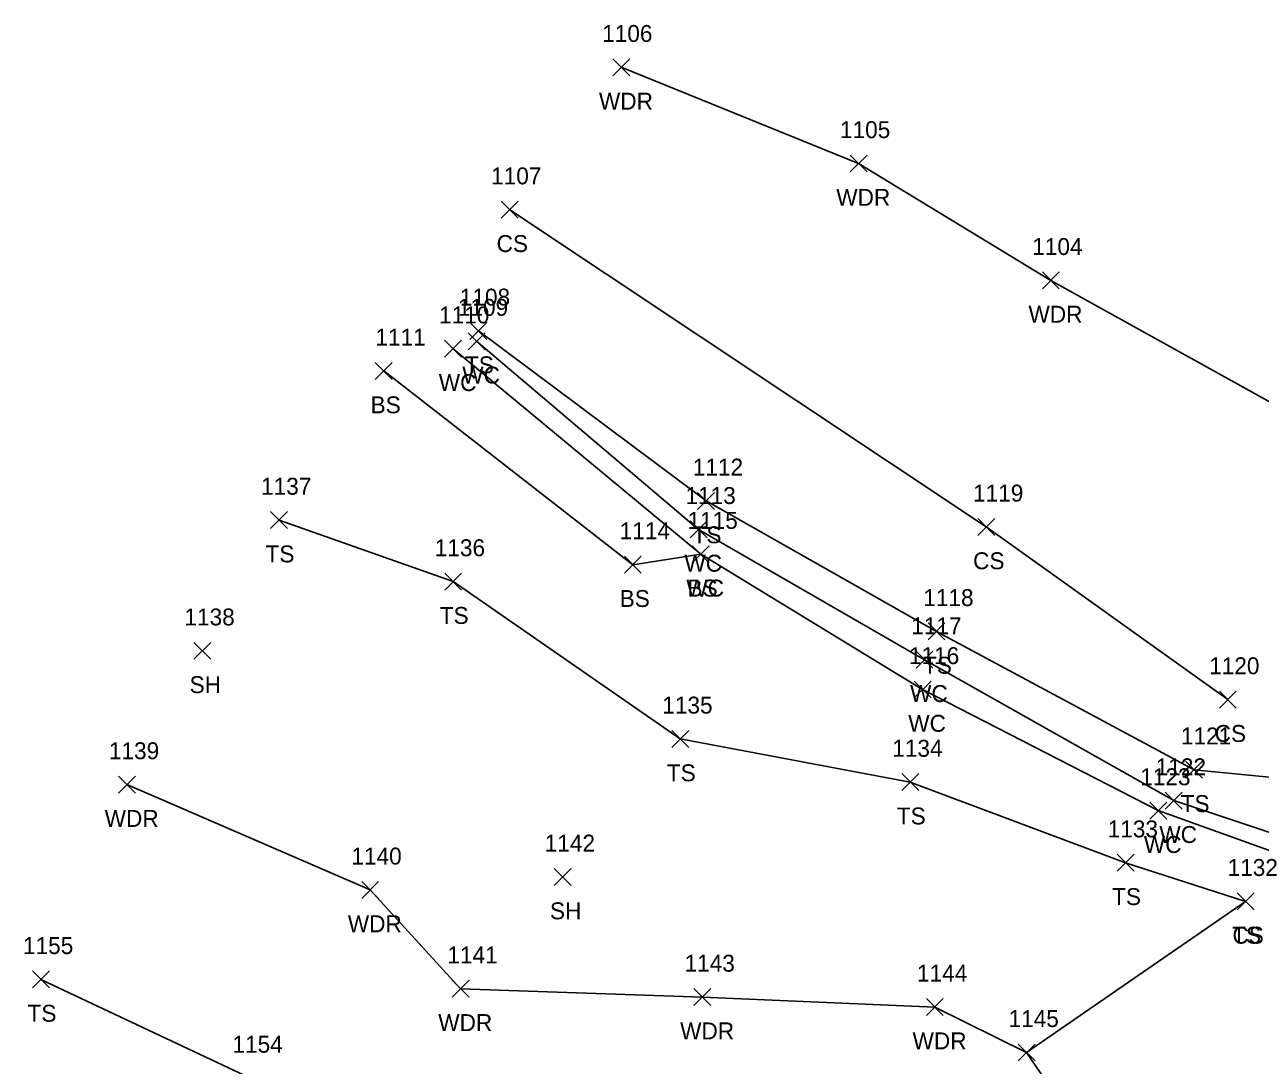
# Model space of a CAD drawing. Extents: x 1640777 to 1641692, y 610911 to 611377.
# Drawn here: x 1641273.4 to 1641419.5, y 611254.1 to 611377.1 of the extents above; entities that cross this region are included whole.
import ezdxf

# ---------------------------------------------------------------- set-up
doc = ezdxf.new("R2010")
doc.units = 0
for name, color, linetype in [('L_A', 7, 'Continuous'), ('L_I', 7, 'Continuous'), ('L_TIC', 7, 'Continuous'), ('LAWA', 7, 'Continuous'), ('LAWE', 7, 'Continuous'), ('LELB', 7, 'Continuous')]:
    doc.layers.add(name, color=color, linetype=linetype)

msp = doc.modelspace()

# ---------------------------------------------------------------- linework, layer by layer
at = {"layer": 'L_TIC'}
for points in [[(1641342.92, 611371.04), (1641344.92, 611373.04)], [(1641344.92, 611371.04), (1641342.92, 611373.04)], [(1641370.98, 611359.67), (1641372.98, 611361.67)], [(1641372.98, 611359.67), (1641370.98, 611361.67)], [(1641329.74, 611354.21), (1641331.74, 611356.21)], [(1641331.74, 611354.21), (1641329.74, 611356.21)], [(1641393.71, 611345.86), (1641395.71, 611347.86)], [(1641395.71, 611345.86), (1641393.71, 611347.86)], [(1641326.03, 611339.88), (1641328.03, 611341.88)], [(1641328.03, 611339.88), (1641326.03, 611341.88)], [(1641325.81, 611338.67), (1641327.81, 611340.67)], [(1641327.81, 611338.67), (1641325.81, 611340.67)], [(1641323.03, 611337.78), (1641325.03, 611339.78)], [(1641325.03, 611337.78), (1641323.03, 611339.78)], [(1641314.84, 611335.15), (1641316.84, 611337.15)], [(1641316.84, 611335.15), (1641314.84, 611337.15)], [(1641352.94, 611319.79), (1641354.94, 611321.79)], [(1641354.94, 611319.79), (1641352.94, 611321.79)], [(1641302.46, 611317.53), (1641304.46, 611319.53)], [(1641304.46, 611317.53), (1641302.46, 611319.53)], [(1641352.07, 611316.43), (1641354.07, 611318.43)], [(1641354.07, 611316.43), (1641352.07, 611318.43)], [(1641386.08, 611316.72), (1641388.08, 611318.72)], [(1641388.08, 611316.72), (1641386.08, 611318.72)], [(1641352.31, 611313.49), (1641354.31, 611315.49)], [(1641354.31, 611313.49), (1641352.31, 611315.49)], [(1641352.31, 611313.49), (1641354.31, 611315.49)], [(1641354.31, 611313.49), (1641352.31, 611315.49)], [(1641344.29, 611312.26), (1641346.29, 611314.26)], [(1641346.29, 611312.26), (1641344.29, 611314.26)], [(1641323.05, 611310.26), (1641325.05, 611312.26)], [(1641325.05, 611310.26), (1641323.05, 611312.26)], [(1641380.19, 611304.37), (1641382.19, 611306.37)], [(1641382.19, 611304.37), (1641380.19, 611306.37)], [(1641293.39, 611302.08), (1641295.39, 611304.08)], [(1641295.39, 611302.08), (1641293.39, 611304.08)], [(1641378.77, 611301.03), (1641380.77, 611303.03)], [(1641380.77, 611301.03), (1641378.77, 611303.03)], [(1641378.55, 611297.51), (1641380.55, 611299.51)], [(1641380.55, 611297.51), (1641378.55, 611299.51)], [(1641414.64, 611296.31), (1641416.64, 611298.31)], [(1641416.64, 611296.31), (1641414.64, 611298.31)], [(1641349.9, 611291.66), (1641351.9, 611293.66)], [(1641351.9, 611291.66), (1641349.9, 611293.66)], [(1641410.65, 611288.02), (1641412.65, 611290.02)], [(1641412.65, 611288.02), (1641410.65, 611290.02)], [(1641284.47, 611286.27), (1641286.47, 611288.27)], [(1641286.47, 611286.27), (1641284.47, 611288.27)], [(1641377.09, 611286.56), (1641379.09, 611288.56)], [(1641379.09, 611286.56), (1641377.09, 611288.56)], [(1641408.24, 611284.37), (1641410.24, 611286.37)], [(1641410.24, 611284.37), (1641408.24, 611286.37)], [(1641406.41, 611283.19), (1641408.41, 611285.19)], [(1641408.41, 611283.19), (1641406.41, 611285.19)], [(1641402.55, 611277.03), (1641404.55, 611279.03)], [(1641404.55, 611277.03), (1641402.55, 611279.03)], [(1641336, 611275.35), (1641338, 611277.35)], [(1641338, 611275.35), (1641336, 611277.35)], [(1641313.23, 611273.82), (1641315.23, 611275.82)], [(1641315.23, 611273.82), (1641313.23, 611275.82)], [(1641416.74, 611272.47), (1641418.74, 611274.47)], [(1641418.74, 611272.47), (1641416.74, 611274.47)], [(1641416.74, 611272.47), (1641418.74, 611274.47)], [(1641418.74, 611272.47), (1641416.74, 611274.47)], [(1641274.31, 611263.24), (1641276.31, 611265.24)], [(1641276.31, 611263.24), (1641274.31, 611265.24)], [(1641323.92, 611262.14), (1641325.92, 611264.14)], [(1641325.92, 611262.14), (1641323.92, 611264.14)], [(1641352.52, 611261.16), (1641354.52, 611263.16)], [(1641354.52, 611261.16), (1641352.52, 611263.16)], [(1641380, 611259.98), (1641382, 611261.98)], [(1641382, 611259.98), (1641380, 611261.98)], [(1641390.84, 611254.61), (1641392.84, 611256.61)], [(1641392.84, 611254.61), (1641390.84, 611256.61)], [(1641390.84, 611254.61), (1641392.84, 611256.61)], [(1641392.84, 611254.61), (1641390.84, 611256.61)]]:
    msp.add_lwpolyline(points, dxfattribs=at)
at = {"layer": 'LAWA'}
for points in [[(1641436.08, 611316.38), (1641422.14, 611331.65), (1641394.71, 611346.86), (1641371.98, 611360.67), (1641343.92, 611372.04)], [(1641285.47, 611287.27), (1641314.23, 611274.82), (1641324.92, 611263.14), (1641353.52, 611262.16), (1641381, 611260.98), (1641391.84, 611255.61), (1641400.01, 611243.67), (1641389.74, 611233.78), (1641364.25, 611234.98), (1641344.03, 611214.73), (1641310.82, 611201.14), (1641274.29, 611183.81)]]:
    msp.add_lwpolyline(points, dxfattribs=at)
at = {"layer": 'LAWE'}
for points in [[(1641324.03, 611338.78), (1641353.31, 611314.49), (1641379.55, 611298.51), (1641407.41, 611284.19), (1641421.99, 611278.95)], [(1641326.81, 611339.67), (1641353.07, 611317.43), (1641379.77, 611302.03), (1641409.24, 611285.37), (1641422.74, 611280.91)]]:
    msp.add_lwpolyline(points, dxfattribs=at)
at = {"layer": 'LELB'}
for points in [[(1641330.74, 611355.21), (1641387.08, 611317.72), (1641415.64, 611297.31)], [(1641327.03, 611340.88), (1641353.94, 611320.79), (1641381.19, 611305.37), (1641411.65, 611289.02), (1641422.13, 611287.97), (1641439.17, 611284.87)], [(1641315.84, 611336.15), (1641345.29, 611313.26), (1641353.31, 611314.49)], [(1641417.74, 611273.47), (1641403.55, 611278.03), (1641378.09, 611287.56), (1641350.9, 611292.66), (1641324.05, 611311.26), (1641303.46, 611318.53)], [(1641417.74, 611273.47), (1641391.84, 611255.61)], [(1641407.01, 611239.25), (1641389.74, 611233.78), (1641377.23, 611238.34), (1641354.4, 611247.12), (1641322.5, 611247.63), (1641300.07, 611252.58), (1641275.31, 611264.24)]]:
    msp.add_lwpolyline(points, dxfattribs=at)

# ---------------------------------------------------------------- texts
at = {"layer": 'L_A'}
for s, p in [('WDR', (1641341.28, 611367.04)), ('WDR', (1641369.34, 611355.67)), ('CS', (1641329.18, 611350.21)), ('WDR', (1641392.07, 611341.86)), ('TS', (1641325.44, 611335.88)), ('WC', (1641322.34, 611333.78)), ('WC', (1641325.12, 611334.67)), ('BS', (1641314.28, 611331.15)), ('TS', (1641352.35, 611315.79)), ('TS', (1641301.86, 611313.53)), ('WC', (1641351.38, 611312.43)), ('CS', (1641385.52, 611312.72)), ('WC', (1641351.61, 611309.49)), ('BS', (1641351.75, 611309.49)), ('BS', (1641343.73, 611308.26)), ('TS', (1641322.46, 611306.26)), ('TS', (1641379.6, 611300.37)), ('SH', (1641292.88, 611298.08)), ('WC', (1641378.07, 611297.03)), ('WC', (1641377.85, 611293.51)), ('CS', (1641414.08, 611292.31)), ('TS', (1641349.31, 611287.66)), ('TS', (1641410.06, 611284.02)), ('TS', (1641376.5, 611282.56)), ('WDR', (1641282.84, 611282.27)), ('WC', (1641407.54, 611280.37)), ('WC', (1641405.71, 611279.19)), ('TS', (1641401.96, 611273.03)), ('SH', (1641335.49, 611271.35)), ('WDR', (1641311.59, 611269.82)), ('TS', (1641416.15, 611268.47)), ('CS', (1641416.18, 611268.47)), ('TS', (1641273.72, 611259.24)), ('WDR', (1641322.28, 611258.14)), ('WDR', (1641350.88, 611257.16)), ('WDR', (1641378.36, 611255.98))]:
    msp.add_text(s, height=2, dxfattribs=at).set_placement(p)
at = {"layer": 'L_I'}
for s, p in [('1106', (1641341.66, 611375.04)), ('1105', (1641369.78, 611363.67)), ('1107', (1641328.53, 611358.21)), ('1104', (1641392.51, 611349.86)), ('1108', (1641324.83, 611343.88)), ('1109', (1641324.6, 611342.67)), ('1110', (1641322.38, 611341.78)), ('1111', (1641314.85, 611339.15)), ('1112', (1641352.38, 611323.79)), ('1137', (1641301.33, 611321.53)), ('1113', (1641351.51, 611320.43)), ('1119', (1641385.51, 611320.72)), ('1115', (1641351.75, 611317.49)), ('1115', (1641351.75, 611317.49)), ('1114', (1641343.73, 611316.26)), ('1136', (1641321.87, 611314.26)), ('1118', (1641379.63, 611308.37)), ('1138', (1641292.27, 611306.08)), ('1117', (1641378.21, 611305.03)), ('1116', (1641377.93, 611301.51)), ('1120', (1641413.43, 611300.31)), ('1135', (1641348.77, 611295.66)), ('1121', (1641410.09, 611292.02)), ('1139', (1641283.34, 611290.27)), ('1134', (1641375.96, 611290.56)), ('1122', (1641407.11, 611288.37)), ('1123', (1641405.28, 611287.19)), ('1133', (1641401.43, 611281.03)), ('1142', (1641334.87, 611279.35)), ('1140', (1641312.01, 611277.82)), ('1132', (1641415.61, 611276.47)), ('1132', (1641415.61, 611276.47)), ('1155', (1641273.18, 611267.24)), ('1141', (1641323.36, 611266.14)), ('1143', (1641351.4, 611265.16)), ('1144', (1641378.88, 611263.98)), ('1145', (1641389.71, 611258.61)), ('1145', (1641389.71, 611258.61)), ('1154', (1641297.95, 611255.58))]:
    msp.add_text(s, height=2, dxfattribs=at).set_placement(p)

doc.saveas('drawing.dxf')
